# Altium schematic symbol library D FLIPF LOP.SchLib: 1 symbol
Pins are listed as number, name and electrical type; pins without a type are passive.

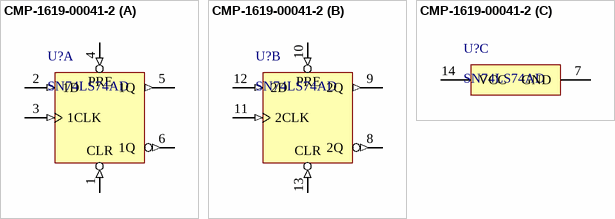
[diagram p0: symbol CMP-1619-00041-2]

## CMP-1619-00041-2
designator U?, comment SN74LS74AD
Dual D-type pos.-edge-triggered flip-flops with preset and clear, D0014A, TUBE; Manufacturer: Texas Instruments; Output Drive (IOL/IOH)(Max)(mA): 8/-0.4; Voltage(Nom)(V): 5; Output: 3S; ICC @ Nom Voltage(Max)(mA): 8; tpd @ Nom Voltage(Max)(ns): 40; Rating: Catalog; VCC(Min)(V): 4.75; Output Type: TTL; Technology Family: LS; VCC(Max)(V): 5.25; Bits(#): 2; Output Logic: Inverted,Non-inverted; 3-State Output: No; F @ Nom Voltage(Max)(Mhz): 35
footprint D0014A_L (SOIC, 14-Leads, Body 8.75x4mm, Pitch 1.27mm, IPC High Density)
footprint D0014A_N (SOIC, 14-Leads, Body 8.75x4mm, Pitch 1.27mm, IPC Medium Density)
footprint D0014A_M (SOIC, 14-Leads, Body 8.75x4mm, Pitch 1.27mm, IPC Low Density)
part A pins: 1 1~{CLR} (in), 2 1D (in), 3 1CLK (in), 4 1~{PRE} (in), 5 1Q (out), 6 1Q (out)
part B pins: 8 2Q (out), 9 2Q (out), 10 2~{PRE} (in), 11 2CLK (in), 12 2D (in), 13 2~{CLR} (in)
part C pins: 7 GND (power), 14 VCC (power)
